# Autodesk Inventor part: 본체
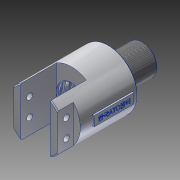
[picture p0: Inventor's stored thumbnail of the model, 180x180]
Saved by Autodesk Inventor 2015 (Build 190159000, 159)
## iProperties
Created: 2019-02
Part Number: 본체
Material: 알루미늄 6061
Document SubType Name: Modeling
Designer: now
Density: 2.7 g/cm^3
Appearance: 알루미늄 - 평지
Mass: 342.301 g
Surface Area: 291.904 cm^2
Volume: 126.778 cm^3
Author: now
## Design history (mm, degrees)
sketch "스케치1"
  geometry: C1 r 13 at (0, 0); 1 further point
  constraints: 1 centre point, 1 coincident
  dimensions: "d1" = 26 diameter of C1
extrude "돌출1" new body sketch "스케치1" distance "d2" = 5; taper "d3" = 0 deg
sketch "스케치2"
  geometry: C1 r 13 at (0, 0) reference; C2 r 15 at (0, 0)
  constraints: 1 centre point, 1 coincident
  dimensions: "d4" = 15 radius of C2
extrude "돌출2" join sketch "스케치2" distance "d5" = 29; taper "d6" = 0 deg
sketch "스케치3"
  geometry: C1 r 13 at (0, 0) reference; C2 r 29 at (0, 0)
  constraints: 1 centre point, 1 coincident
  dimensions: "d7" = 29 radius of C2
extrude "돌출3" join sketch "스케치3" distance "d8" = 38; taper "d9" = 0 deg
feature "스레드1" dims "d10" = 10, "d11" = 0
chamfer "모따기1" distance "d12" = 1; stored, may be unused: second distance "d13" = 2, angle "d14" = 45 deg
sketch "스케치6"
  geometry: L1 (0, -13)-(0, -29) reference; L2 (0, -29)-(-38, -29) reference; L3 (-38, -29)-(-38, 29) reference; L4 (-38, 29)-(0, 29) reference; L5 (0, 29)-(0, 13) reference; L6 (0, 13)-(5, 13) reference; L7 (5, 13)-(5, 15) reference; L8 (5, 15)-(33, 15) reference; L9 (33, 15)-(34, 14) reference; L10 (34, 14)-(34, -14) reference; L11 (34, -14)-(33, -15) reference; L12 (33, -15)-(5, -15) reference; L13 (5, -15)-(5, -13) reference; L14 (5, -13)-(0, -13) reference; L15 (-38, 14)-(-35.35, 14); L16 (-35.35, 14)-(-35.35, 17); L17 (-35.35, 17)-(-30.65, 17); L18 (-30.65, 17)-(-30.65, 14); L19 (-30.65, 14)-(-26.35, 14); L20 (-26.35, 14)-(-26.35, 17); L21 (-26.35, 17)-(-21.65, 17); L22 (-21.65, 17)-(-21.65, 14); L23 (-21.65, 14)-(-18, 14); L24 (-18, 14)-(-18, 16); L25 (-18, 16)-(-11, 16); L26 (-11, 16)-(-11, 0); L27 (-11, 0)-(-38, 0); L28 (-38, 29)-(-38, -29) reference; L29 (-38, 14)-(-38, 0); 5 further points
  constraints: 28 end point, 8 perpendicular, 7 point on line, 3 midpoint, 2 coincident, 2 horizontal, 1 collinear
  dimensions: "d15" = 4.7 distance of L16.end L17.end; "d16" = 4.7 distance of L20.end L21.end; "d17" = 2.35 distance of L16.end point (-33, 17); "d18" = 2.35 distance of L20.end point (-24, 17); "d19" = 9 distance of point (-24, 17) point (-33, 17); "d20" = 5 horizontal distance of L15.start point (-33, 17); "d21" = 28 diameter of L15.start L27; "d22" = 34 diameter of L16.end L27; "d23" = 32 diameter of L25.end L27; "d24" = 7 distance of L24.end L25.end; "d90" = 27 horizontal distance of L15.start L25.end
revolve "회전1" sketch "스케치6" stored, may be unused: angle "d26" = 90 deg
chamfer "모따기2" distance "d27" = 1; stored, may be unused: second distance "d28" = 2, angle "d29" = 45 deg
chamfer "모따기3" distance "d30" = 1; stored, may be unused: second distance "d31" = 2, angle "d32" = 45 deg
sketch "스케치7"
  geometry: C1 r 29 at (0, 0) reference; C2 r 17 at (0, 0) reference; C3 r 29 at (0, 0)
  constraints: 1 centre point, 1 coincident
  dimensions: "d33" = 29 radius of C3
extrude "돌출4" join sketch "스케치7" distance "d34" = 36; taper "d35" = 0 deg
sketch "스케치8"
  geometry: L1 (-15, -38)-(15, -38) reference; L2 (-29, -74)-(29, -74) reference; L3 (-15, -74)-(15, -74); L4 (15, -74)-(15, -38); L5 (15, -38)-(-15, -38); L6 (-15, -38)-(-15, -74); 2 further points
  constraints: 8 end point, 2 midpoint, 2 parallel, 1 horizontal, 1 perpendicular
  dimensions: "d36" = 30 distance of L4.end L5.end; "d37" = 36 distance of L3.end L4.end
extrude "돌출5" cut sketch "스케치8" stored distance "d38" = 36; taper "d39" = 0 deg
sketch "스케치9"
  geometry: L1 (15, 24.819)-(15, -24.819) reference; L2 (22, 0)-(22, -18.894); L3 (22, 0)-(22, 18.894); L4 (22, 18.894)-(22, -18.894); A1 r 29 centre (0, 0) between (15, -24.819) and (15, 24.819) reference; A2 r 18.894 centre (22, 0) between (22, -18.894) and (22, 18.894); 1 further point
  constraints: 6 end point, 4 point on circle, 1 centre point, 1 coincident, 1 horizontal alignment, 1 vertical
  dimensions: "d40" = 7 distance from line of point (22, 0) L1; "d41" = 180 deg angle of L2 L3
extrude "돌출6" cut sketch "스케치9" distance "d42" = 16; taper "d43" = 0 deg
node "작업 평면1"
sketch "스케치11"
  geometry: L1 (0, 28)-(0, -28) reference; L2 (-45, 5)-(-5, 5); L3 (-5, 5)-(-5, -5); L4 (-5, -5)-(-45, -5); L5 (-45, -5)-(-45, 5); 3 further points
  constraints: 8 end point, 2 midpoint, 2 parallel, 1 horizontal, 1 horizontal alignment, 1 perpendicular
  dimensions: "d49" = 5 distance between parallel lines of L1 L3; "d50" = 40 distance of L2.start L2.end; "d51" = 10 distance of L4.end L2.start
extrude "돌출7" join sketch "스케치11" stored distance "d52" = 0; taper "d53" = 0 deg
sketch "스케치12"
  geometry: 4 further points
  constraints: 1 other
  dimensions: "d54" = 20 vertical distance of point (-5, -45) point (0, -25); "d55" = 5 horizontal distance of point (5, -45) point (0, -25)
feature "엠보싱1" sketch "스케치12" dims "d56" = 0.5, "d57" = 0
chamfer "모따기4" distance "d58" = 1; stored, may be unused: second distance "d59" = 2, angle "d60" = 45 deg
sketch "스케치13"
  geometry: L1 (42.538, -16)-(-4.749, -16) reference; L2 (18.894, 58)-(18.894, -16); C1 r 3 at (9.894, -7); C2 r 3 at (27.894, -7); 1 further point
  constraints: 2 centre point, 2 end point, 1 midpoint, 1 other
  dimensions: "d67" = 18 distance of C2.centre C1.centre; "d68" = 6 diameter of C2; "d69" = 9 vertical distance of point (36.215, -16) C2.centre
extrude "돌출8" cut sketch "스케치13" distance "d70" = 15; taper "d71" = 0 deg
chamfer "모따기5" distance "d72" = 1; stored, may be unused: second distance "d73" = 2, angle "d74" = 45 deg
fillet "모깎기1" dims "d75" = 0.8
sketch "스케치14"
  geometry: C1 r 16 at (0, 0) reference
hole "구멍1" sketch "스케치14" at (0, 0) diameter "d76" = 8; stored, may be unused: countersink angle "d80" = 90 deg, drill point angle "d82" = 0 deg; dims "d77" = 6, "d78" = 4, "d79" = 2, "d81" = 23
sketch "스케치15"
  geometry: C1 r 14 at (0, 0) reference
hole "구멍2" sketch "스케치15" at (0, 0) diameter "d83" = 12.376; stored, may be unused: countersink angle "d87" = 90 deg, drill point angle "d89" = 118 deg; dims "d84" = 18, "d85" = 4, "d86" = 2, "d88" = 22
node "솔리드1"
mirror "대칭1"
mirror "대칭2"
node "절단 모서리 투영1"
